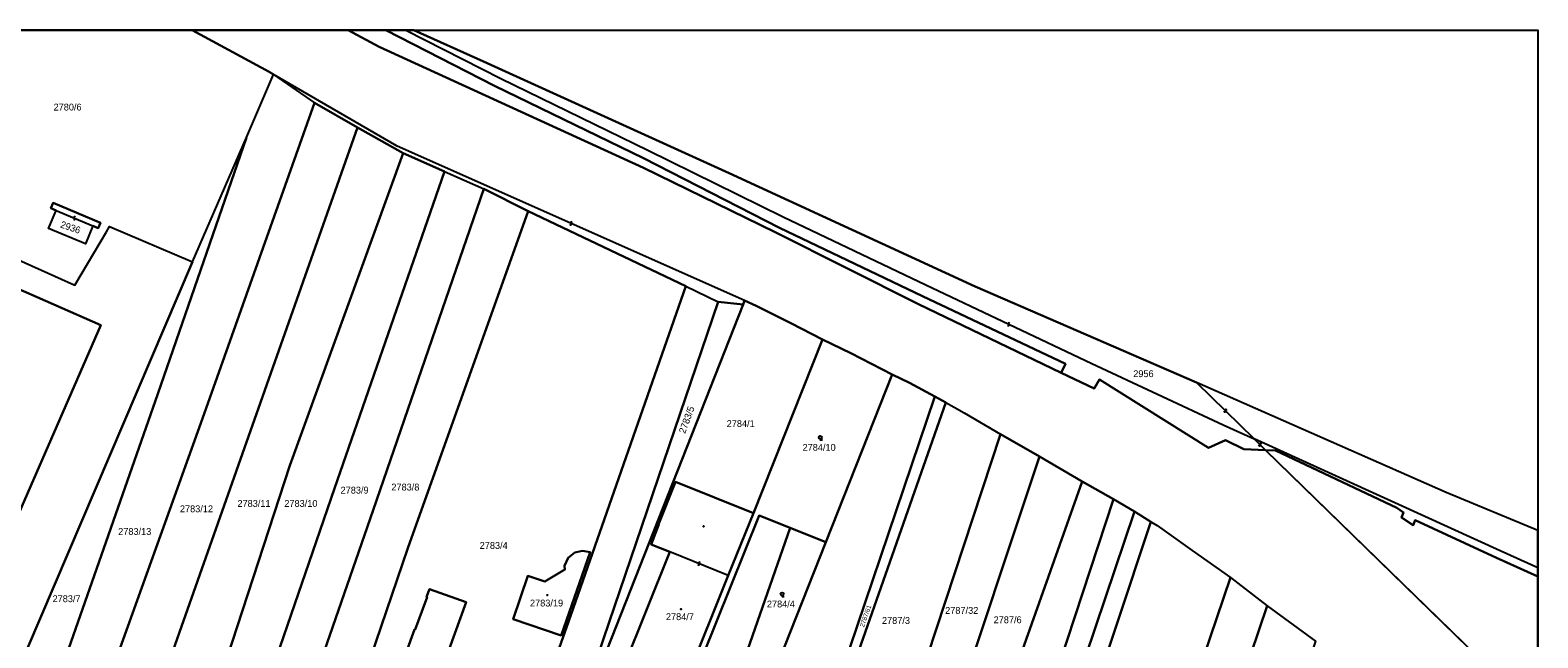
# Model space of a CAD drawing. Extents: x -596024 to -594475, y -1163820 to -1161957.
# Drawn here: x -594849.5 to -594475.5, y -1162107.7 to -1161956.9 of the extents above; entities that cross this region are included whole.
import ezdxf

# ---------------------------------------------------------------- set-up
doc = ezdxf.new("R2010")
doc.units = 0
for name, color, linetype in [('Level 1', 7, 'Continuous'), ('Level 13', 7, 'Continuous'), ('Level 3', 7, 'Continuous'), ('Level 4', 7, 'Continuous'), ('Level 5', 7, 'Continuous'), ('Level 60', 7, 'Continuous'), ('Vrstva 60', 7, 'Continuous'), ('Vrstva 63', 7, 'Continuous')]:
    doc.layers.add(name, color=color, linetype=linetype)

msp = doc.modelspace()

# ---------------------------------------------------------------- linework, layer by layer
at = {"layer": 'Level 1'}
msp.add_line((-594543.01, -1162061.07), (-594475.47, -1162126.88), dxfattribs=at)
for points in [[(-594809.35, -1161956.88), (-594790.21, -1161967.23), (-594789.11, -1161967.85)], [(-594770.63, -1161956.88), (-594762.96, -1161960.99), (-594697.33, -1161991.01), (-594664.67, -1162007.02), (-594629.16, -1162024.91), (-594593.72, -1162041.93)], [(-594593.72, -1162041.93), (-594592.67, -1162039.7), (-594628.15, -1162022.91), (-594663.65, -1162005.95), (-594697.38, -1161988.66), (-594734.32, -1161970.66), (-594761.26, -1161956.88)], [(-594754.33, -1161956.88), (-594737.06, -1161964.7), (-594676.08, -1161992.33), (-594615.09, -1162020.47), (-594560.18, -1162044.33)], [(-594795.84, -1161983.5), (-594789.11, -1161967.85)], [(-594789.11, -1161967.85), (-594778.96, -1161974.89)], [(-594841.52, -1162150.04), (-594806.77, -1162053.21), (-594778.96, -1161974.89)], [(-594768.31, -1161981.07), (-594778.96, -1161974.89)], [(-594829.67, -1162155.07), (-594795.88, -1162059.09), (-594768.31, -1161981.07)], [(-594756.96, -1161987.43), (-594768.31, -1161981.07)], [(-594852.23, -1162145.49), (-594817.81, -1162047.12), (-594795.84, -1161983.5)], [(-594809.23, -1162014.4), (-594795.84, -1161983.5)], [(-594756.96, -1161987.43), (-594785.13, -1162064.92), (-594816.34, -1162160.73)], [(-594746.76, -1161991.96), (-594756.96, -1161987.43)], [(-594806.44, -1162164.93), (-594773.98, -1162070.58), (-594746.76, -1161991.96)], [(-594746.76, -1161991.96), (-594736.99, -1161996.29)], [(-594890.22, -1161996.88), (-594874.7, -1162003.85), (-594838.41, -1162020.17), (-594830.59, -1162006.94), (-594829.79, -1162005.61), (-594809.23, -1162014.4)], [(-594736.99, -1161996.29), (-594764.38, -1162075.96), (-594796.68, -1162169.08)], [(-594725.97, -1162001.77), (-594736.99, -1161996.29)], [(-594833.95, -1162005.44), (-594832.64, -1162005.99), (-594832.09, -1162004.68), (-594843.82, -1161999.77), (-594844.37, -1162001.08), (-594843.06, -1162001.63)], [(-594833.95, -1162005.44), (-594835.82, -1162009.9), (-594844.93, -1162006.09), (-594843.06, -1162001.63)], [(-594785.91, -1162173.65), (-594783.72, -1162167.34), (-594755.8, -1162085.45), (-594725.97, -1162001.77)], [(-594686.86, -1162020.42), (-594725.97, -1162001.77)], [(-594860.38, -1162095.01), (-594831.95, -1162030.05), (-594878.68, -1162009.54), (-594907.14, -1162074.5), (-594904.91, -1162075.48), (-594909.82, -1162086.72), (-594865.55, -1162106.4), (-594860.38, -1162095.01)], [(-594857.29, -1162126.68), (-594809.23, -1162014.4)], [(-594746.55, -1162190.06), (-594744.22, -1162183.48), (-594715.97, -1162103.7), (-594686.86, -1162020.42)], [(-594686.86, -1162020.42), (-594678.79, -1162024.27)], [(-594678.79, -1162024.27), (-594707.27, -1162107.93), (-594719.29, -1162143.25)], [(-594672.66, -1162024.92), (-594719.29, -1162143.25)], [(-594672.66, -1162024.92), (-594678.79, -1162024.27)], [(-594672.29, -1162023.99), (-594672.66, -1162024.92)], [(-594652.94, -1162033.66), (-594660.77, -1162029.59), (-594669.42, -1162025.29), (-594672.29, -1162023.99)], [(-594670.08, -1162076.73), (-594652.94, -1162033.66)], [(-594635.64, -1162042.29), (-594645.88, -1162037), (-594652.94, -1162033.66)], [(-594635.64, -1162042.29), (-594652.12, -1162083.97)], [(-594625.07, -1162047.82), (-594631.38, -1162044.42), (-594635.64, -1162042.29)], [(-594593.72, -1162041.93), (-594585.57, -1162045.79), (-594584.21, -1162043.61), (-594557.16, -1162060.51), (-594552.98, -1162058.64), (-594548.42, -1162060.86), (-594543.01, -1162061.07)], [(-594475.47, -1162081.04), (-594498.22, -1162071.61), (-594560.18, -1162044.33)], [(-594655.49, -1162137.69), (-594653.97, -1162133.18), (-594625.07, -1162047.82)], [(-594652.32, -1162134.66), (-594622.36, -1162049.29)], [(-594622.36, -1162049.29), (-594625.07, -1162047.82)], [(-594622.36, -1162049.29), (-594620.24, -1162050.44), (-594617.76, -1162051.84), (-594608.8, -1162057.12)], [(-594608.8, -1162057.12), (-594631.56, -1162126.18)], [(-594599.13, -1162062.65), (-594608.8, -1162057.12)], [(-594599.13, -1162062.65), (-594621.71, -1162130.49)], [(-594588.55, -1162068.92), (-594599.13, -1162062.65)], [(-594543.01, -1162061.07), (-594540.52, -1162061.16), (-594510.45, -1162075.4), (-594508.82, -1162076.57), (-594509.3, -1162077.85), (-594506.44, -1162079.71), (-594505.9, -1162078.51), (-594485.7, -1162087.83), (-594475.47, -1162092.44)], [(-594670.08, -1162076.73), (-594689.38, -1162068.95), (-594693.66, -1162079.53), (-594693.52, -1162079.58), (-594695.45, -1162084.52), (-594690.83, -1162086.35)], [(-594611.65, -1162134.22), (-594588.55, -1162068.92)], [(-594580.78, -1162073.28), (-594588.55, -1162068.92)], [(-594601.86, -1162137.48), (-594580.78, -1162073.28)], [(-594575.5, -1162076.32), (-594580.78, -1162073.28)], [(-594661, -1162080.39), (-594668.68, -1162077.29), (-594686.29, -1162121.17), (-594697.81, -1162149.73), (-594718.63, -1162202.1)], [(-594676.33, -1162092.19), (-594670.08, -1162076.73)], [(-594575.5, -1162076.32), (-594604.58, -1162162.45), (-594628.68, -1162233.25)], [(-594571.48, -1162078.93), (-594596.99, -1162155.53)], [(-594571.48, -1162078.93), (-594575.5, -1162076.32)], [(-594571.48, -1162078.93), (-594569.93, -1162079.76), (-594561.26, -1162086.02), (-594551.69, -1162092.73)], [(-594705.43, -1162207.92), (-594675.94, -1162123.29), (-594661, -1162080.39)], [(-594652.12, -1162083.97), (-594661, -1162080.39)], [(-594717.74, -1162107.11), (-594729.72, -1162103.01), (-594726.03, -1162092.29), (-594721.83, -1162093.72), (-594716.87, -1162090.71), (-594716.96, -1162089.8), (-594716.03, -1162087.85), (-594714.42, -1162086.52), (-594712.47, -1162086.08), (-594710.56, -1162086.44), (-594717.74, -1162107.11)], [(-594690.83, -1162086.35), (-594702.24, -1162114.75)], [(-594701.73, -1162209.41), (-594652.12, -1162083.97)], [(-594686.49, -1162117.62), (-594676.33, -1162092.19)], [(-594551.69, -1162092.73), (-594575.44, -1162162.74)], [(-594551.69, -1162092.73), (-594542.59, -1162099.77)], [(-594758.59, -1162117.97), (-594754.13, -1162105.57), (-594753.96, -1162105.63), (-594751.01, -1162097.57), (-594751.2, -1162097.5), (-594750.44, -1162095.57), (-594741.34, -1162098.82), (-594749.44, -1162121.24)], [(-594595.16, -1162254.67), (-594571.04, -1162183.94), (-594542.59, -1162099.77)], [(-594542.59, -1162099.77), (-594530.64, -1162108.54)]]:
    msp.add_lwpolyline(points, dxfattribs=at)
at = {"layer": 'Level 13'}
for centre, start, end in [((-594838.58, -1162003.71), 194.4625, 67.0525), ((-594838.44, -1162003.37), 14.677, 246.775), ((-594715.44, -1162005.01), 193.3961, 65.4941), ((-594715.28, -1162004.67), 13.1816, 245.7716), ((-594606.83, -1162030.05), 191.7852, 64.3752), ((-594606.67, -1162029.71), 11.9997, 244.0976), ((-594553.13, -1162051.46), 172.8855, 45.4755), ((-594552.87, -1162051.2), 353.1, 225.198), ((-594544.55, -1162059.83), 172.8809, 45.4709), ((-594544.29, -1162059.57), 353.0953, 225.1933), ((-594683.65, -1162089.44), 195.4352, 67.5332), ((-594683.51, -1162089.1), 15.2207, 247.8107)]:
    msp.add_arc(centre, 0.184, start, end, dxfattribs=at)
at = {"layer": 'Level 3'}
for points in [[(-594756.31, -1161956.88), (-594732.76, -1161968.85), (-594696.24, -1161986.7), (-594662.72, -1162003.18), (-594627.34, -1162020.11), (-594586.16, -1162039.64), (-594553.52, -1162054.83), (-594545.82, -1162058.33)], [(-594672.29, -1162023.99), (-594758.43, -1161985.68), (-594789.11, -1161967.85)], [(-594843.06, -1162001.63), (-594833.95, -1162005.44)], [(-594560.18, -1162044.33), (-594545.82, -1162058.33)], [(-594475.47, -1162090.33), (-594484.82, -1162086.11), (-594510.07, -1162074.59), (-594545.82, -1162058.33)], [(-594545.82, -1162058.33), (-594543.01, -1162061.07)], [(-594676.33, -1162092.19), (-594690.83, -1162086.35)]]:
    msp.add_lwpolyline(points, dxfattribs=at)
at = {"layer": 'Level 5'}
for points in [[(-594653.48, -1162058.33), (-594653.48, -1162058.58), (-594652.98, -1162058.58)], [(-594662.95, -1162097.18), (-594662.95, -1162097.43), (-594662.45, -1162097.43)]]:
    msp.add_lwpolyline(points, dxfattribs=at)
for centre, radius in [((-594653.48, -1162057.96), 0.375), ((-594682.43, -1162080), 0.09), ((-594682.43, -1162080), 0.0521), ((-594721.21, -1162097.06), 0.09), ((-594721.21, -1162097.06), 0.0521), ((-594662.95, -1162096.81), 0.375), ((-594688.03, -1162100.58), 0.09), ((-594688.03, -1162100.58), 0.0521)]:
    msp.add_circle(centre, radius, dxfattribs=at)
at = {"layer": 'Level 60'}
for points in [[(-594806.77, -1162053.21), (-594841.52, -1162150.04), (-594852.23, -1162145.49), (-594817.81, -1162047.12), (-594795.84, -1161983.5), (-594789.11, -1161967.85), (-594778.96, -1161974.89)], [(-594795.88, -1162059.09), (-594829.67, -1162155.07), (-594841.52, -1162150.04), (-594806.77, -1162053.21), (-594778.96, -1161974.89), (-594768.31, -1161981.07)], [(-594768.31, -1161981.07), (-594756.96, -1161987.43), (-594785.13, -1162064.92), (-594816.34, -1162160.73), (-594826.54, -1162156.4), (-594829.67, -1162155.07), (-594795.88, -1162059.09)], [(-594817.81, -1162047.12), (-594852.23, -1162145.49), (-594862.25, -1162141.24), (-594857.29, -1162126.68), (-594809.23, -1162014.4), (-594795.84, -1161983.5)], [(-594806.44, -1162164.93), (-594816.34, -1162160.73), (-594785.13, -1162064.92), (-594756.96, -1161987.43), (-594746.76, -1161991.96), (-594773.98, -1162070.58)], [(-594736.99, -1161996.29), (-594764.38, -1162075.96), (-594796.68, -1162169.08), (-594806.44, -1162164.93), (-594773.98, -1162070.58), (-594746.76, -1161991.96)], [(-594861.45, -1162136.02), (-594935.08, -1162105.7), (-594930.49, -1162089.91), (-594898.57, -1162015.96), (-594890.22, -1161996.88), (-594874.7, -1162003.85), (-594838.41, -1162020.17), (-594830.59, -1162006.94), (-594829.79, -1162005.61), (-594809.23, -1162014.4), (-594857.29, -1162126.68)], [(-594755.8, -1162085.45), (-594783.72, -1162167.34), (-594785.91, -1162173.65), (-594787.2, -1162173.1), (-594796.68, -1162169.08), (-594764.38, -1162075.96), (-594736.99, -1161996.29), (-594725.97, -1162001.77)], [(-594832.64, -1162005.99), (-594833.95, -1162005.44), (-594835.82, -1162009.9), (-594844.93, -1162006.09), (-594843.06, -1162001.63), (-594844.37, -1162001.08), (-594843.82, -1161999.77), (-594832.09, -1162004.68)], [(-594783.72, -1162167.34), (-594755.8, -1162085.45), (-594725.97, -1162001.77), (-594686.86, -1162020.42), (-594715.97, -1162103.7), (-594744.22, -1162183.48), (-594746.55, -1162190.06), (-594757.22, -1162185.61), (-594768.79, -1162180.79), (-594785.91, -1162173.65)], [(-594860.38, -1162095.01), (-594831.95, -1162030.05), (-594878.68, -1162009.54), (-594907.14, -1162074.5), (-594904.91, -1162075.48), (-594909.82, -1162086.72), (-594865.55, -1162106.4)], [(-594831.95, -1162030.05), (-594860.38, -1162095.01), (-594865.55, -1162106.4), (-594909.82, -1162086.72), (-594904.91, -1162075.48), (-594907.14, -1162074.5), (-594878.68, -1162009.54)], [(-594719.29, -1162143.25), (-594739.01, -1162193.28), (-594740.72, -1162192.55), (-594746.55, -1162190.06), (-594744.22, -1162183.48), (-594715.97, -1162103.7), (-594686.86, -1162020.42), (-594678.79, -1162024.27), (-594707.27, -1162107.93)], [(-594672.66, -1162024.92), (-594719.29, -1162143.25), (-594707.27, -1162107.93), (-594678.79, -1162024.27)], [(-594652.12, -1162083.97), (-594661, -1162080.39), (-594668.68, -1162077.29), (-594686.29, -1162121.17), (-594697.81, -1162149.73), (-594718.63, -1162202.1), (-594720, -1162201.49), (-594707.12, -1162168.93), (-594706.66, -1162167.77), (-594699.2, -1162149.17), (-594687.68, -1162120.61), (-594686.49, -1162117.62), (-594676.33, -1162092.19), (-594670.08, -1162076.73), (-594652.94, -1162033.66), (-594645.88, -1162037), (-594635.64, -1162042.29)], [(-594689.64, -1162214.64), (-594697.18, -1162211.23), (-594701.73, -1162209.41), (-594652.12, -1162083.97), (-594635.64, -1162042.29), (-594631.38, -1162044.42), (-594625.07, -1162047.82), (-594653.97, -1162133.18), (-594655.49, -1162137.69), (-594667.25, -1162133.63), (-594675.19, -1162156.64), (-594678.9, -1162155.36), (-594685.92, -1162175.69), (-594674.83, -1162179.48), (-594670.08, -1162165.57), (-594665.39, -1162167.12), (-594682.35, -1162217.53)], [(-594620.24, -1162050.44), (-594617.76, -1162051.84), (-594608.8, -1162057.12), (-594631.56, -1162126.18), (-594637.59, -1162144.45), (-594664.76, -1162225.02), (-594669.86, -1162222.85), (-594681.39, -1162217.94), (-594663.86, -1162167.62), (-594660.9, -1162168.93), (-594666.62, -1162181.86), (-594655.69, -1162186.69), (-594649.91, -1162173.6), (-594656.22, -1162170.81), (-594654.73, -1162167.43), (-594652.98, -1162166.81), (-594650.6, -1162161.3), (-594648.2, -1162162.34), (-594638.75, -1162140.64), (-594641.26, -1162139.53), (-594652.32, -1162134.66), (-594622.36, -1162049.29)], [(-594622.36, -1162049.29), (-594652.32, -1162134.66), (-594653.61, -1162138.34), (-594655.49, -1162137.69), (-594653.97, -1162133.18), (-594625.07, -1162047.82)], [(-594608.8, -1162057.12), (-594599.13, -1162062.65), (-594621.71, -1162130.49), (-594623.46, -1162129.72), (-594631.56, -1162126.18)], [(-594599.13, -1162062.65), (-594588.55, -1162068.92), (-594611.65, -1162134.22), (-594617.88, -1162132.15), (-594621.71, -1162130.49)], [(-594693.06, -1162118.44), (-594702.24, -1162114.75), (-594690.83, -1162086.35), (-594695.45, -1162084.52), (-594693.52, -1162079.58), (-594693.66, -1162079.53), (-594689.38, -1162068.95), (-594670.08, -1162076.73), (-594676.33, -1162092.19), (-594686.49, -1162117.62), (-594687.68, -1162120.61)], [(-594588.55, -1162068.92), (-594580.78, -1162073.28), (-594601.86, -1162137.48), (-594602.37, -1162137.31), (-594611.65, -1162134.22)], [(-594630.7, -1162239.18), (-594634.99, -1162237.5), (-594609.23, -1162159.9), (-594601.86, -1162137.48), (-594580.78, -1162073.28), (-594575.5, -1162076.32), (-594604.58, -1162162.45), (-594628.68, -1162233.25)], [(-594675.94, -1162123.29), (-594705.43, -1162207.92), (-594713.96, -1162204.17), (-594718.63, -1162202.1), (-594697.81, -1162149.73), (-594686.29, -1162121.17), (-594668.68, -1162077.29), (-594661, -1162080.39)], [(-594575.5, -1162076.32), (-594571.48, -1162078.93), (-594596.99, -1162155.53), (-594598.65, -1162154.97), (-594601.83, -1162164.39), (-594611.52, -1162192.71), (-594612.3, -1162192.44), (-594612.66, -1162193.48), (-594611.88, -1162193.75), (-594618.12, -1162212), (-594618.95, -1162214.46), (-594616.95, -1162215.18), (-594623.72, -1162235.42), (-594628.68, -1162233.25), (-594604.58, -1162162.45)], [(-594569.93, -1162079.76), (-594561.26, -1162086.02), (-594551.69, -1162092.73), (-594575.44, -1162162.74), (-594596.99, -1162155.53), (-594571.48, -1162078.93)], [(-594705.43, -1162207.92), (-594675.94, -1162123.29), (-594661, -1162080.39), (-594652.12, -1162083.97), (-594701.73, -1162209.41)], [(-594729.72, -1162103.01), (-594717.74, -1162107.11), (-594710.56, -1162086.44), (-594712.47, -1162086.08), (-594714.42, -1162086.52), (-594716.03, -1162087.85), (-594716.96, -1162089.8), (-594716.87, -1162090.71), (-594721.83, -1162093.72), (-594726.03, -1162092.29)], [(-594717.74, -1162107.11), (-594729.72, -1162103.01), (-594726.03, -1162092.29), (-594721.83, -1162093.72), (-594716.87, -1162090.71), (-594716.96, -1162089.8), (-594716.03, -1162087.85), (-594714.42, -1162086.52), (-594712.47, -1162086.08), (-594710.56, -1162086.44)], [(-594571.04, -1162183.94), (-594595.16, -1162254.67), (-594604.98, -1162250.48), (-594603.58, -1162246.52), (-594603.46, -1162246.24), (-594594.77, -1162220.59), (-594585.01, -1162192.07), (-594582.99, -1162189.81), (-594574, -1162163.22), (-594575.44, -1162162.74), (-594551.69, -1162092.73), (-594542.59, -1162099.77)], [(-594542.59, -1162099.77), (-594530.64, -1162108.54), (-594558.36, -1162190.54), (-594582.4, -1162260.11), (-594595.16, -1162254.67), (-594571.04, -1162183.94)]]:
    msp.add_lwpolyline(points, close=True, dxfattribs=at)
for points in [[(-594719.29, -1162143.25), (-594672.66, -1162024.92), (-594672.29, -1162023.99), (-594669.42, -1162025.29), (-594660.77, -1162029.59), (-594652.94, -1162033.66), (-594670.08, -1162076.73), (-594689.38, -1162068.95), (-594693.66, -1162079.53), (-594693.52, -1162079.58), (-594695.45, -1162084.52), (-594690.83, -1162086.35), (-594702.24, -1162114.75)], [(-594749.44, -1162121.24), (-594741.34, -1162098.82), (-594750.44, -1162095.57), (-594751.2, -1162097.5), (-594751.01, -1162097.57), (-594753.96, -1162105.63), (-594754.13, -1162105.57), (-594758.59, -1162117.97)], [(-594758.59, -1162117.97), (-594754.13, -1162105.57), (-594753.96, -1162105.63), (-594751.01, -1162097.57), (-594751.2, -1162097.5), (-594750.44, -1162095.57), (-594741.34, -1162098.82), (-594749.44, -1162121.24)]]:
    msp.add_lwpolyline(points, dxfattribs=at)
at = {"layer": 'Vrstva 60'}
for points in [[(-594809.35, -1161956.88), (-594883.93, -1161956.88), (-594888.52, -1161975.95), (-594890.22, -1161996.88), (-594874.7, -1162003.85), (-594838.41, -1162020.17), (-594830.59, -1162006.94), (-594829.79, -1162005.61), (-594809.23, -1162014.4), (-594795.84, -1161983.5), (-594789.11, -1161967.85), (-594790.21, -1161967.23)], [(-594761.26, -1161956.88), (-594770.63, -1161956.88), (-594762.96, -1161960.99), (-594697.33, -1161991.01), (-594664.67, -1162007.02), (-594629.16, -1162024.91), (-594593.72, -1162041.93), (-594592.67, -1162039.7), (-594628.15, -1162022.91), (-594663.65, -1162005.95), (-594697.38, -1161988.66), (-594734.32, -1161970.66)], [(-594475.47, -1162092.44), (-594475.47, -1162081.04), (-594498.22, -1162071.61), (-594560.18, -1162044.33), (-594615.09, -1162020.47), (-594676.08, -1161992.33), (-594737.06, -1161964.7), (-594754.33, -1161956.88), (-594761.26, -1161956.88), (-594734.32, -1161970.66), (-594697.38, -1161988.66), (-594663.65, -1162005.95), (-594628.15, -1162022.91), (-594592.67, -1162039.7), (-594593.72, -1162041.93), (-594585.57, -1162045.79), (-594584.21, -1162043.61), (-594557.16, -1162060.51), (-594552.98, -1162058.64), (-594548.42, -1162060.86), (-594543.01, -1162061.07), (-594540.52, -1162061.16), (-594510.45, -1162075.4), (-594508.82, -1162076.57), (-594509.3, -1162077.85), (-594506.44, -1162079.71), (-594505.9, -1162078.51), (-594485.7, -1162087.83)], [(-594835.82, -1162009.9), (-594844.93, -1162006.09), (-594843.06, -1162001.63), (-594844.37, -1162001.08), (-594843.82, -1161999.77), (-594832.09, -1162004.68), (-594832.64, -1162005.99), (-594833.95, -1162005.44)], [(-594475.47, -1162126.88), (-594475.47, -1162092.44), (-594485.7, -1162087.83), (-594505.9, -1162078.51), (-594506.44, -1162079.71), (-594509.3, -1162077.85), (-594508.82, -1162076.57), (-594510.45, -1162075.4), (-594540.52, -1162061.16), (-594543.01, -1162061.07)]]:
    msp.add_lwpolyline(points, close=True, dxfattribs=at)
msp.add_lwpolyline([(-594475.47, -1162126.88), (-594543.01, -1162061.07), (-594548.42, -1162060.86), (-594552.98, -1162058.64), (-594557.16, -1162060.51), (-594584.21, -1162043.61), (-594585.57, -1162045.79), (-594593.72, -1162041.93), (-594629.16, -1162024.91), (-594664.67, -1162007.02), (-594697.33, -1161991.01), (-594762.96, -1161960.99), (-594770.63, -1161956.88), (-594809.35, -1161956.88), (-594790.21, -1161967.23), (-594789.11, -1161967.85), (-594778.96, -1161974.89), (-594768.31, -1161981.07), (-594756.96, -1161987.43), (-594746.76, -1161991.96), (-594736.99, -1161996.29), (-594725.97, -1162001.77), (-594686.86, -1162020.42), (-594678.79, -1162024.27), (-594672.66, -1162024.92), (-594672.29, -1162023.99), (-594669.42, -1162025.29), (-594660.77, -1162029.59), (-594652.94, -1162033.66), (-594645.88, -1162037), (-594635.64, -1162042.29), (-594631.38, -1162044.42), (-594625.07, -1162047.82), (-594622.36, -1162049.29), (-594620.24, -1162050.44), (-594617.76, -1162051.84), (-594608.8, -1162057.12), (-594599.13, -1162062.65), (-594588.55, -1162068.92), (-594580.78, -1162073.28), (-594575.5, -1162076.32), (-594571.48, -1162078.93), (-594569.93, -1162079.76), (-594561.26, -1162086.02), (-594551.69, -1162092.73), (-594542.59, -1162099.77), (-594530.64, -1162108.54)], dxfattribs=at)
at = {"layer": 'Vrstva 63'}
msp.add_lwpolyline([(-594475.47, -1163820.23), (-596024.42, -1163820.23), (-596024.42, -1161956.88), (-594475.47, -1161956.88)], close=True, dxfattribs=at)

# ---------------------------------------------------------------- texts
at = {"layer": 'Level 4'}
for s, p in [('2780/6', (-594843.71, -1161976.82)), ('2956', (-594575.85, -1162042.98)), ('2784/1', (-594676.71, -1162055.37)), ('2784/10', (-594657.89, -1162061.26)), ('2783/9', (-594772.5, -1162071.88)), ('2783/8', (-594759.9, -1162071.11)), ('2783/12', (-594812.36, -1162076.51)), ('2783/11', (-594798.09, -1162075.18)), ('2783/10', (-594786.46, -1162075.18)), ('2783/13', (-594827.68, -1162082.14)), ('2783/4', (-594737.99, -1162085.6)), ('2783/7', (-594843.96, -1162098.82)), ('2783/19', (-594725.51, -1162099.89)), ('2784/7', (-594691.79, -1162103.28)), ('2784/4', (-594666.74, -1162100.13)), ('2787/32', (-594622.51, -1162101.72)), ('2787/3', (-594638.19, -1162104.22)), ('2787/6', (-594610.49, -1162104.05))]:
    msp.add_text(s, height=1.7, dxfattribs=at).set_placement(p)
for s, height, rotation, p in [('2936', 1.7, 341.2185, (-594842.17, -1162005.8)), ('2783/5', 1.7, 69.9953, (-594687.04, -1162057.13)), ('2787/61', 1.14, 70.6823, (-594642.67, -1162105.14))]:
    msp.add_text(s, height=height, rotation=rotation, dxfattribs=at).set_placement(p)

doc.saveas('drawing.dxf')
